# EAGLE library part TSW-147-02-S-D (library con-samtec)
THROUGH-HOLE .025" SQ POST HEADER Source: Samtec TSW.pdf
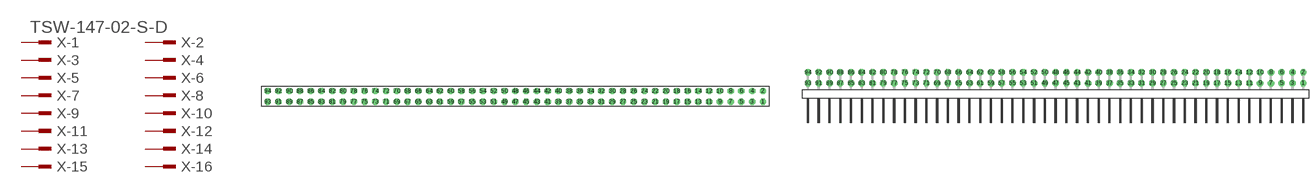
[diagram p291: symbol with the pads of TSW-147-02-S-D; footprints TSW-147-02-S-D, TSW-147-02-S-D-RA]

Designator prefix X; gates -1=MPINV -2=MPIN -3=MPIN -4=MPIN -5=MPIN -6=MPIN -7=MPIN -8=MPIN -9=MPIN -10=MPIN -11=MPIN -12=MPIN -13=MPIN -14=MPIN -15=MPIN -16=MPIN -17=MPIN -18=MPIN -19=MPIN -20=MPIN -21=MPIN -22=MPIN -23=MPIN -24=MPIN -25=MPIN -26=MPIN -27=MPIN -28=MPIN -29=MPIN -30=MPIN -31=MPIN -32=MPIN -33=MPIN -34=MPIN -35=MPIN -36=MPIN -37=MPIN -38=MPIN -39=MPIN -40=MPIN -41=MPIN -42=MPIN -43=MPIN -44=MPIN -45=MPIN -46=MPIN -47=MPIN -48=MPIN -49=MPIN -50=MPIN -51=MPIN -52=MPIN -53=MPIN -54=MPIN -55=MPIN -56=MPIN -57=MPIN -58=MPIN -59=MPIN -60=MPIN -61=MPIN -62=MPIN -63=MPIN -64=MPIN -65=MPIN -66=MPIN -67=MPIN -68=MPIN -69=MPIN -70=MPIN -71=MPIN -72=MPIN -73=MPIN -74=MPIN -75=MPIN -76=MPIN -77=MPIN -78=MPIN -79=MPIN -80=MPIN -81=MPIN -82=MPIN -83=MPIN -84=MPIN -85=MPIN -86=MPIN -87=MPIN -88=MPIN -89=MPIN -90=MPIN -91=MPIN -92=MPIN -93=MPIN -94=MPIN

## TSW-147-02-S-D (OC_FARNELL: unknown; OC_NEWARK: unknown)  [TSW-147-02-S-D]
1  -1:1  pas
2  -2:1  pas
3  -3:1  pas
4  -4:1  pas
5  -5:1  pas
6  -6:1  pas
7  -7:1  pas
8  -8:1  pas
9  -9:1  pas
10  -10:1  pas
11  -11:1  pas
12  -12:1  pas
13  -13:1  pas
14  -14:1  pas
15  -15:1  pas
16  -16:1  pas
17  -17:1  pas
18  -18:1  pas
19  -19:1  pas
20  -20:1  pas
21  -21:1  pas
22  -22:1  pas
23  -23:1  pas
24  -24:1  pas
25  -25:1  pas
26  -26:1  pas
27  -27:1  pas
28  -28:1  pas
29  -29:1  pas
30  -30:1  pas
31  -31:1  pas
32  -32:1  pas
33  -33:1  pas
34  -34:1  pas
35  -35:1  pas
36  -36:1  pas
37  -37:1  pas
38  -38:1  pas
39  -39:1  pas
40  -40:1  pas
41  -41:1  pas
42  -42:1  pas
43  -43:1  pas
44  -44:1  pas
45  -45:1  pas
46  -46:1  pas
47  -47:1  pas
48  -48:1  pas
49  -49:1  pas
50  -50:1  pas
51  -51:1  pas
52  -52:1  pas
53  -53:1  pas
54  -54:1  pas
55  -55:1  pas
56  -56:1  pas
57  -57:1  pas
58  -58:1  pas
59  -59:1  pas
60  -60:1  pas
61  -61:1  pas
62  -62:1  pas
63  -63:1  pas
64  -64:1  pas
65  -65:1  pas
66  -66:1  pas
67  -67:1  pas
68  -68:1  pas
69  -69:1  pas
70  -70:1  pas
71  -71:1  pas
72  -72:1  pas
73  -73:1  pas
74  -74:1  pas
75  -75:1  pas
76  -76:1  pas
77  -77:1  pas
78  -78:1  pas
79  -79:1  pas
80  -80:1  pas
81  -81:1  pas
82  -82:1  pas
83  -83:1  pas
84  -84:1  pas
85  -85:1  pas
86  -86:1  pas
87  -87:1  pas
88  -88:1  pas
89  -89:1  pas
90  -90:1  pas
91  -91:1  pas
92  -92:1  pas
93  -93:1  pas
94  -94:1  pas

## TSW-147-02-S-D-RA (OC_FARNELL: unknown; OC_NEWARK: unknown)  [TSW-147-02-S-D-RA]
Pads as for TSW-147-02-S-D

## Footprint TSW-147-02-S-D (pad centres in mm)
THROUGH-HOLE .025" SQ POST HEADER Source: Samtec TSW.pdf
drill 1 pad 1.5 octagon: 1 58.42,-1.27; 2 58.42,1.27; 3 55.88,-1.27; 4 55.88,1.27; 5 53.34,-1.27; 6 53.34,1.27; 7 50.8,-1.27; 8 50.8,1.27; 9 48.26,-1.27; 10 48.26,1.27; 11 45.72,-1.27; 12 45.72,1.27; 13 43.18,-1.27; 14 43.18,1.27; 15 40.64,-1.27; 16 40.64,1.27; 17 38.1,-1.27; 18 38.1,1.27; 19 35.56,-1.27; 20 35.56,1.27; 21 33.02,-1.27; 22 33.02,1.27; 23 30.48,-1.27; 24 30.48,1.27; 25 27.94,-1.27; 26 27.94,1.27; 27 25.4,-1.27; 28 25.4,1.27; 29 22.86,-1.27; 30 22.86,1.27; 31 20.32,-1.27; 32 20.32,1.27; 33 17.78,-1.27; 34 17.78,1.27; 35 15.24,-1.27; 36 15.24,1.27; 37 12.7,-1.27; 38 12.7,1.27; 39 10.16,-1.27; 40 10.16,1.27; 41 7.62,-1.27; 42 7.62,1.27; 43 5.08,-1.27; 44 5.08,1.27; 45 2.54,-1.27; 46 2.54,1.27; 47 0,-1.27; 48 0,1.27; 49 -2.54,-1.27; 50 -2.54,1.27; 51 -5.08,-1.27; 52 -5.08,1.27; 53 -7.62,-1.27; 54 -7.62,1.27; 55 -10.16,-1.27; 56 -10.16,1.27; 57 -12.7,-1.27; 58 -12.7,1.27; 59 -15.24,-1.27; 60 -15.24,1.27; 61 -17.78,-1.27; 62 -17.78,1.27; 63 -20.32,-1.27; 64 -20.32,1.27; 65 -22.86,-1.27; 66 -22.86,1.27; 67 -25.4,-1.27; 68 -25.4,1.27; 69 -27.94,-1.27; 70 -27.94,1.27; 71 -30.48,-1.27; 72 -30.48,1.27; 73 -33.02,-1.27; 74 -33.02,1.27; 75 -35.56,-1.27; 76 -35.56,1.27; 77 -38.1,-1.27; 78 -38.1,1.27; 79 -40.64,-1.27; 80 -40.64,1.27; 81 -43.18,-1.27; 82 -43.18,1.27; 83 -45.72,-1.27; 84 -45.72,1.27; 85 -48.26,-1.27; 86 -48.26,1.27; 87 -50.8,-1.27; 88 -50.8,1.27; 89 -53.34,-1.27; 90 -53.34,1.27; 91 -55.88,-1.27; 92 -55.88,1.27; 93 -58.42,-1.27; 94 -58.42,1.27

## Footprint TSW-147-02-S-D-RA (pad centres in mm)
THROUGH-HOLE .025" SQ POST HEADER Source: Samtec TSW.pdf
drill 1 pad 1.5 octagon: 1 58.42,1.524; 2 58.42,4.064; 3 55.88,1.524; 4 55.88,4.064; 5 53.34,1.524; 6 53.34,4.064; 7 50.8,1.524; 8 50.8,4.064; 9 48.26,1.524; 10 48.26,4.064; 11 45.72,1.524; 12 45.72,4.064; 13 43.18,1.524; 14 43.18,4.064; 15 40.64,1.524; 16 40.64,4.064; 17 38.1,1.524; 18 38.1,4.064; 19 35.56,1.524; 20 35.56,4.064; 21 33.02,1.524; 22 33.02,4.064; 23 30.48,1.524; 24 30.48,4.064; 25 27.94,1.524; 26 27.94,4.064; 27 25.4,1.524; 28 25.4,4.064; 29 22.86,1.524; 30 22.86,4.064; 31 20.32,1.524; 32 20.32,4.064; 33 17.78,1.524; 34 17.78,4.064; 35 15.24,1.524; 36 15.24,4.064; 37 12.7,1.524; 38 12.7,4.064; 39 10.16,1.524; 40 10.16,4.064; 41 7.62,1.524; 42 7.62,4.064; 43 5.08,1.524; 44 5.08,4.064; 45 2.54,1.524; 46 2.54,4.064; 47 0,1.524; 48 0,4.064; 49 -2.54,1.524; 50 -2.54,4.064; 51 -5.08,1.524; 52 -5.08,4.064; 53 -7.62,1.524; 54 -7.62,4.064; 55 -10.16,1.524; 56 -10.16,4.064; 57 -12.7,1.524; 58 -12.7,4.064; 59 -15.24,1.524; 60 -15.24,4.064; 61 -17.78,1.524; 62 -17.78,4.064; 63 -20.32,1.524; 64 -20.32,4.064; 65 -22.86,1.524; 66 -22.86,4.064; 67 -25.4,1.524; 68 -25.4,4.064; 69 -27.94,1.524; 70 -27.94,4.064; 71 -30.48,1.524; 72 -30.48,4.064; 73 -33.02,1.524; 74 -33.02,4.064; 75 -35.56,1.524; 76 -35.56,4.064; 77 -38.1,1.524; 78 -38.1,4.064; 79 -40.64,1.524; 80 -40.64,4.064; 81 -43.18,1.524; 82 -43.18,4.064; 83 -45.72,1.524; 84 -45.72,4.064; 85 -48.26,1.524; 86 -48.26,4.064; 87 -50.8,1.524; 88 -50.8,4.064; 89 -53.34,1.524; 90 -53.34,4.064; 91 -55.88,1.524; 92 -55.88,4.064; 93 -58.42,1.524; 94 -58.42,4.064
